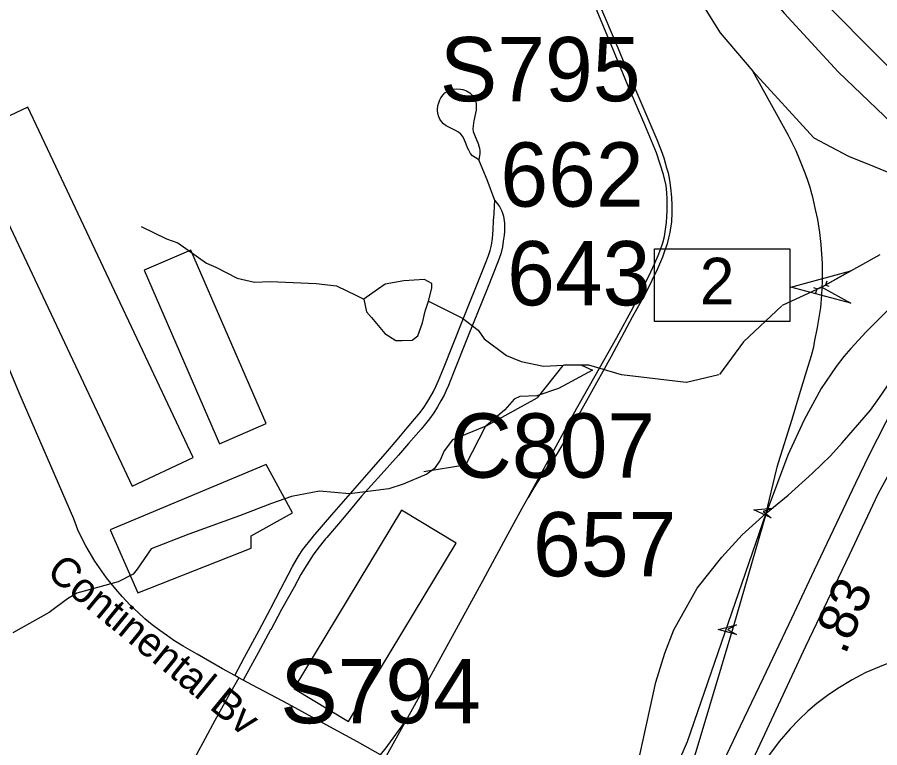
# Model space of a CAD drawing. Extents: x 1383679 to 1536984, y 460658 to 651027.
# Drawn here: x 1423468 to 1426243, y 504390 to 506739 of the extents above; entities that cross this region are included whole.
import ezdxf

# ---------------------------------------------------------------- set-up
doc = ezdxf.new("R2010")
doc.units = 0
for name, color, linetype in [('Exist Cultural Warehouse Building Footprint', 7, 'Continuous'), ('Exist Hydrographic Creek Single Shore', 7, 'Continuous'), ('Exist Hydrographic Misc Water Feature', 7, 'Continuous'), ('Exist Railroad Spur', 7, 'Continuous'), ('Exist Road Non-System Type 51', 7, 'Continuous'), ('Exist Road Non-System Type 51 Label', 7, 'Continuous'), ('Exist Road Primary Interstate Divided Center Attributed', 7, 'Continuous'), ('Exist Road Primary Interstate Interchange CELL', 7, 'Continuous'), ('Exist Road Primary Interstate Ramp 1 Lane Attributed', 7, 'Continuous'), ('Exist Road Primary Interstate Structure Ovrhead Sign Attributed CELL', 7, 'Continuous'), ('Exist Road Primary Interstate Structure Ovrhead Sign Number Label', 7, 'Continuous'), ('Exist Road Secondary Mileage Hundredths English Label', 7, 'Continuous'), ('Exist Road Secondary Structure Culvert Attributed CELL', 7, 'Continuous'), ('Exist Road Secondary Structure Culvert CELL', 7, 'Continuous'), ('Exist Road Secondary Structure Culvert Number Label', 7, 'Continuous'), ('Exist Road Secondary Structure Standard Bridge Attributed CELL', 7, 'Continuous'), ('Exist Road Secondary Structure Standard Bridge Number Label', 7, 'Continuous')]:
    doc.layers.add(name, color=color, linetype=linetype)

msp = doc.modelspace()

# ---------------------------------------------------------------- linework, layer by layer
at = {"layer": 'Exist Cultural Warehouse Building Footprint'}
for points in [[(1423837.8, 505230.9), (1424033.9, 505323.4), (1423502.3, 506450.1), (1423306.1, 506357.6), (1423837.8, 505230.9)], [(1424119, 505367.2), (1424268.9, 505432.3), (1424026.6, 505990.6), (1423876.7, 505925.6), (1424119, 505367.2)], [(1423767.5, 505090.6), (1423855.9, 504888), (1424221.4, 505032.2), (1424221.4, 505071.1), (1424354, 505145.2), (1424269.6, 505301), (1423767.5, 505090.6)], [(1424358, 504580.2), (1424533.9, 504474), (1424880.2, 505047.8), (1424704.2, 505153.9), (1424358, 504580.2)]]:
    msp.add_lwpolyline(points, dxfattribs=at)
at = {"layer": 'Exist Hydrographic Creek Single Shore'}
for p, q in [((1425928.2, 505811.6), (1425805, 505695.4)), ((1425804.6, 505694.9), (1425727.7, 505590)), ((1425224.1, 505619.6), (1425140.6, 505515.2)), ((1425305.9, 505620.8), (1425226.6, 505620.8)), ((1425412.1, 505589.1), (1425306.8, 505620.7)), ((1425620.4, 505564.3), (1425412.7, 505589)), ((1425725.8, 505588.7), (1425621.5, 505564.4)), ((1425139.6, 505514.4), (1424974.9, 505423.2)), ((1424973.6, 505421.8), (1424911.2, 505300.3)), ((1424908.8, 505298.6), (1424776.1, 505277.6))]:
    msp.add_line(p, q, dxfattribs=at)
msp.add_lwpolyline([(1426243.1, 505974.7), (1426056.9, 505871.7), (1425928.9, 505812.1)], dxfattribs=at)
at = {"layer": 'Exist Hydrographic Misc Water Feature'}
for points in [[(1423867.5, 506066.4), (1423948.7, 506026.2), (1423984.5, 506014), (1424077.4, 505948.1), (1424107, 505935.2), (1424176.4, 505900.2), (1424232.2, 505886.8), (1424282.2, 505889.8), (1424430.2, 505882.8), (1424496, 505875.7), (1424559.6, 505844.9), (1424583.3, 505832.1)], [(1424791.3, 505826.3), (1424802, 505867.9), (1424802.4, 505883.5), (1424778.7, 505896.2), (1424712.5, 505891.8), (1424652.3, 505880.8), (1424627.9, 505863.2), (1424583.3, 505832.1)], [(1424583.3, 505832.1), (1424592.5, 505791.7), (1424608.2, 505773.3), (1424651.1, 505722.4), (1424686.8, 505699.6), (1424706.8, 505700), (1424738.8, 505700.9), (1424757, 505714.5), (1424771.9, 505756.1), (1424780.6, 505794.5), (1424791.3, 505826.3)], [(1424791.3, 505826.3), (1424900.3, 505771.5), (1424951.4, 505732.8), (1424971, 505704.5), (1425042, 505651.4), (1425089.6, 505632.3), (1425161.4, 505617), (1425247.5, 505621), (1425283.5, 505620.2), (1425319.2, 505603.9)], [(1425319.2, 505603.9), (1425210, 505545.4), (1425139.5, 505521.4), (1425085.4, 505520), (1425067.2, 505510.5), (1425036.5, 505476.7), (1424975.5, 505424.6), (1424868.6, 505379.9), (1424841.9, 505344.3), (1424829.3, 505315.1), (1424810.8, 505287.5), (1424786.5, 505270), (1424709.8, 505237.1), (1424663.4, 505222.4), (1424537, 505206.9), (1424441.2, 505214.6), (1424350.8, 505198.4), (1424286.3, 505175.8), (1424183.5, 505135.2), (1424020.3, 505077), (1423899.2, 505029.4), (1423854, 504963.8), (1423841.7, 504948.4), (1423793.2, 504923.2), (1423660.4, 504887.3), (1423630, 504868.2), (1423571.2, 504825.1), (1423453.8, 504759.3)]]:
    msp.add_lwpolyline(points, dxfattribs=at)
at = {"layer": 'Exist Railroad Spur'}
for points in [[(1425344.8, 506771.7), (1425395.2, 506653.5), (1425428.9, 506573.8), (1425461.7, 506496.6), (1425526.5, 506346), (1425539.7, 506310.7), (1425548.3, 506287), (1425552.9, 506271.4), (1425557.4, 506254.8), (1425562.1, 506239.1), (1425566.6, 506215.3), (1425570.4, 506190.7), (1425572.9, 506161.1), (1425574.5, 506134.3), (1425574.3, 506111.3), (1425572.7, 506080.1), (1425570.4, 506062.1), (1425567.6, 506047.3), (1425564, 506029.5), (1425558.8, 506011), (1425552.1, 505990.2), (1425543.9, 505967.6), (1425528.2, 505929.9), (1425491.6, 505854.8), (1425446.6, 505775), (1425378.8, 505648.4), (1425304.8, 505515.5), (1425280.3, 505471.5), (1425230.6, 505380.6), (1425215.8, 505353.9), (1425204.9, 505336), (1425192.9, 505316.8), (1425178.3, 505295.2), (1425159.7, 505269.5), (1425143.6, 505245.9), (1425130.7, 505225.3), (1425112.3, 505194.9)], [(1425112.3, 505194.9), (1425208.4, 505371.1), (1425268.9, 505482.3), (1425327.9, 505585.5), (1425396.9, 505709.7), (1425450.1, 505806.3), (1425478.9, 505864.7), (1425500.3, 505906.5), (1425520.1, 505948.7), (1425530.8, 505972.7), (1425538.1, 505992.5), (1425545.8, 506013.3), (1425550.8, 506034.5), (1425553.7, 506056.4), (1425557.3, 506078.8), (1425558.3, 506098.6), (1425559.1, 506116.2), (1425559.6, 506135.9), (1425558.9, 506155.8), (1425558.2, 506174.5), (1425555.7, 506198.3), (1425547.7, 506233.5), (1425525.4, 506303.2), (1425487.6, 506393.1), (1425433.3, 506518.2), (1425381.8, 506643.6), (1425330.3, 506766.2)], [(1424231.6, 503586.9), (1424279, 503674.4), (1424343.4, 503791.2), (1424398.6, 503892.2), (1424468, 504020.3), (1424543.5, 504159.4), (1424575.2, 504216.5), (1424620.2, 504298.3), (1424746.3, 504525.6), (1424966.8, 504928.9), (1425041.8, 505066), (1425093.3, 505160.2), (1425112.3, 505194.9)], [(1424723.1, 504483.8), (1424650.5, 504385.2), (1424602.5, 504328.2), (1424567.9, 504276.9), (1424542.9, 504242.5), (1424531.8, 504224.4), (1424497.7, 504163.7), (1424264.4, 503732.7), (1424228, 503665.9)]]:
    msp.add_lwpolyline(points, dxfattribs=at)
at = {"layer": 'Exist Road Non-System Type 51'}
for p, q in [((1424181.4, 504614.8), (1424168.4, 504621.8)), ((1424194.7, 504607.6), (1424181.4, 504614.8))]:
    msp.add_line(p, q, dxfattribs=at)
for points in [[(1424953.7, 506280.3), (1424941.5, 506287.8), (1424933.2, 506293.9), (1424926.7, 506301.1), (1424920.7, 506311.3), (1424917.4, 506319.1), (1424912.3, 506331.4), (1424904.6, 506349.2), (1424900.3, 506356.9), (1424895.5, 506363.2), (1424887.8, 506369.3), (1424877.9, 506375.2), (1424861.1, 506383.4), (1424848.1, 506390.3), (1424839.4, 506396.7), (1424833.1, 506403.6), (1424828, 506411.5), (1424824.3, 506418.9), (1424821.6, 506430.1), (1424820.8, 506441.9), (1424821.9, 506455.9), (1424824.5, 506464.6), (1424828, 506474.1), (1424831.4, 506480.4), (1424838.3, 506489.7), (1424844.3, 506495.8), (1424851.1, 506500.4), (1424861.4, 506505.6), (1424871.3, 506507.9), (1424881.2, 506508.7), (1424894.1, 506507.9), (1424902.1, 506506.8), (1424913.8, 506502.6), (1424924.5, 506495.8), (1424932.8, 506487.8), (1424938.8, 506480), (1424943.4, 506468.8), (1424945.3, 506458.8), (1424945, 506449.5), (1424944.4, 506440.7), (1424943, 506430.7), (1424937.4, 506406.6), (1424935.9, 506399.4), (1424934.7, 506389.1), (1424934.3, 506380.4), (1424935.5, 506372.4), (1424938.9, 506361.4), (1424952, 506329.7), (1424952.6, 506328.4), (1424956, 506317.8), (1424956.7, 506310.2), (1424956.7, 506301.1), (1424953.7, 506280.3)], [(1425004.7, 506149.9), (1424980.3, 506216.3), (1424960.7, 506262.1), (1424953.7, 506280.3)], [(1424168.4, 504621.8), (1424199.6, 504680.6), (1424246.1, 504765.3), (1424282.9, 504836.6), (1424283.8, 504838.3), (1424316.3, 504901), (1424339.9, 504945.8), (1424354.1, 504973.2), (1424373.1, 505006.2), (1424387.1, 505027.4), (1424417.9, 505066), (1424420.3, 505069.1), (1424480.3, 505138.7), (1424540.1, 505207), (1424608.1, 505284.7), (1424659.4, 505343.4), (1424690.2, 505379.7), (1424722.8, 505419.2), (1424746.8, 505447.1), (1424764.5, 505468.4), (1424776.2, 505483.9), (1424786.1, 505498.7), (1424795.6, 505515.6), (1424807.1, 505535.6), (1424814.8, 505551.2), (1424823.9, 505571.5), (1424839.6, 505609.9), (1424901.6, 505766.2), (1424965.3, 505923.5), (1424978.2, 505955.6), (1424984.5, 505972.7), (1424989.4, 505988.7), (1424993.9, 506006.6), (1424997.4, 506027.8), (1424999.3, 506055.5), (1425001, 506085.4), (1425002.2, 506105.8), (1425004.1, 506132.5), (1425004.7, 506149.9)], [(1425004.7, 506149.9), (1425019.7, 506130.7), (1425027.4, 506115.3), (1425032.7, 506099.5), (1425035.7, 506077.5), (1425035.7, 506050.2), (1425034.6, 506038.1), (1425032.1, 506019.1), (1425029.1, 506001.4), (1425023.9, 505978.2), (1425016, 505955.3), (1424981, 505867.7), (1424919.2, 505714.5), (1424871, 505593.2), (1424855.5, 505555.2), (1424848.1, 505538.8), (1424841.4, 505524.3), (1424831.5, 505505.7), (1424820.3, 505486.6), (1424808.1, 505467.4), (1424794.6, 505448), (1424782.1, 505431.4), (1424767.7, 505414.8), (1424751.8, 505396.1), (1424726.9, 505367.9), (1424694.8, 505330.4), (1424639.1, 505268.9), (1424576.1, 505199.4), (1424520.2, 505131.7), (1424464.7, 505066), (1424460.6, 505061.2), (1424435.7, 505030.2), (1424420.7, 505010.2), (1424392.1, 504966.5), (1424381, 504946.9), (1424359.8, 504905.8), (1424319, 504834.2), (1424283.8, 504768.8), (1424283.6, 504768.5), (1424243.5, 504695.2), (1424194.7, 504607.6)], [(1424168.4, 504621.8), (1424128.4, 504643.3), (1424047, 504690.6), (1424002.5, 504716.1), (1423972.6, 504734.9), (1423948.3, 504751.5), (1423927.2, 504766.6), (1423902.9, 504785.6), (1423878.7, 504804.8), (1423857.1, 504824.8), (1423831.2, 504848.8), (1423805.8, 504876.4), (1423785.3, 504900.1), (1423755.4, 504936.6), (1423718.1, 504990.3), (1423689.5, 505039), (1423675.3, 505066), (1423663.6, 505090.6), (1423650.1, 505125.7), (1423477.8, 505523.3), (1423371.5, 505776)], [(1424181.4, 504614.8), (1424147.4, 504554.6), (1424104.4, 504477.1), (1424073.4, 504419.7), (1424043.5, 504366), (1424011.7, 504308), (1423971.9, 504234.6), (1423932.7, 504162.4), (1423895.7, 504096.1), (1423839.9, 503992.8), (1423786.4, 503895.7), (1423746.2, 503820.4), (1423704, 503743.1), (1423651.9, 503650.8), (1423612.7, 503579.4), (1423567.7, 503498.5), (1423538.9, 503446.5), (1423512.9, 503400), (1423485.8, 503350.7), (1423442.9, 503272.5), (1423418.8, 503227.1), (1423393.7, 503181.5), (1423342, 503081.6), (1423316.7, 503038.4)], [(1424687.6, 504338), (1424644.1, 504363), (1424563.1, 504408.6), (1424462.5, 504463.7), (1424338.6, 504531.5), (1424283.8, 504560.3), (1424224.9, 504591.3), (1424194.7, 504607.6)]]:
    msp.add_lwpolyline(points, dxfattribs=at)
at = {"layer": 'Exist Road Primary Interstate Divided Center Attributed'}
for points in [[(1425073.4, 508070.3), (1425293.2, 507637.6), (1425399, 507455), (1425518.2, 507280.7), (1425633.3, 507115.8), (1425745.3, 506973.6), (1425935.9, 506752.3), (1426109.3, 506564), (1426283.5, 506397.8), (1426408.3, 506282.1), (1426521.5, 506191.5)], [(1426691.7, 506209.6), (1426568.6, 506307.6), (1426490.9, 506377.1), (1426275.2, 506575.2), (1426031.5, 506822.2), (1425828.3, 507066), (1425685.2, 507251.7), (1425537.9, 507462.3)], [(1426686.3, 506014.4), (1426599.7, 505864.5), (1426542.3, 505765.1), (1426506.1, 505699.7), (1426377.5, 505463.2), (1426237.1, 505204.9), (1426144.4, 505009.5), (1426004.8, 504715.5), (1425865.1, 504416.2), (1425744.8, 504158.5), (1425456.4, 503554.4)], [(1426549.7, 505962.5), (1426486, 505856.1), (1426410, 505717.1), (1426340.7, 505590.2), (1426207.5, 505329.8), (1426165, 505240.3), (1426032.4, 504960.5), (1425959.1, 504805.7), (1425867.8, 504613.3)], [(1425867.8, 504613.3), (1425781.7, 504432.3), (1425720.5, 504303.8), (1425682.7, 504218.4), (1425644.1, 504136.5), (1425483.6, 503795.2), (1425457.6, 503740), (1425410.2, 503650.8), (1425369.5, 503582.5), (1425316.7, 503493.1), (1425248.8, 503376.6), (1425114.8, 503176.5)]]:
    msp.add_lwpolyline(points, dxfattribs=at)
at = {"layer": 'Exist Road Primary Interstate Interchange CELL'}
msp.add_lwpolyline([(1425518.9, 505994.1), (1425953.9, 505994.1), (1425953.9, 505760.9), (1425518.9, 505760.9)], close=True, dxfattribs=at)
at = {"layer": 'Exist Road Primary Interstate Ramp 1 Lane Attributed'}
for points in [[(1425073.4, 508070.3), (1425105.5, 507938.5), (1425226.8, 507621), (1425349.2, 507339.9), (1425453.7, 507130.1), (1425729.9, 506688.9), (1425835, 506566.3)], [(1425835, 506566.3), (1426031.5, 506352), (1426142.7, 506292.4), (1426225.3, 506258.9), (1426334.2, 506214.2), (1426412.4, 506199.7), (1426521.5, 506191.5)], [(1426043, 505741.6), (1426053.1, 505805.7), (1426057.3, 505847), (1426059.1, 505889.9), (1426059.1, 505947.4), (1426054.9, 506008.2), (1426050.1, 506046.9), (1426043.7, 506089.1), (1426036.5, 506120.6), (1426027.5, 506160.3), (1426025.1, 506170.9), (1426018.8, 506191.7), (1426011.2, 506217.1), (1426003.5, 506237.8), (1425986.3, 506280.7), (1425974.6, 506309.9), (1425949.3, 506359.1), (1425835, 506566.3)], [(1426686.3, 506040.2), (1426674.4, 506036.2), (1426630, 506020.2), (1426590.9, 506003.9), (1426514.2, 505968.2), (1426446.8, 505930.6), (1426409.6, 505907.2), (1426349.2, 505865.8), (1426288.9, 505817), (1426259, 505787.3), (1426199.1, 505727.8), (1426149.8, 505674.1), (1426128, 505648.2), (1426103.1, 505616), (1426054.9, 505545.3), (1426000.2, 505444.6), (1425947.7, 505330.8), (1425878.2, 505144.8)], [(1425878.2, 505144.8), (1425948, 505201.8), (1426026.7, 505273.3), (1426055.7, 505301.1), (1426084.7, 505328.9), (1426122.5, 505370.6), (1426178.9, 505436.2), (1426213, 505476), (1426240.6, 505513.3), (1426268.6, 505553.8), (1426323.8, 505639.6), (1426369.6, 505715), (1426474.5, 505887.9), (1426506.5, 505940.6)], [(1425878.2, 505144.8), (1425910.9, 505283.2), (1425913.2, 505292.2), (1425917.6, 505306.9), (1425961.6, 505446.6), (1425988.7, 505536.2), (1426013.1, 505616.9), (1426023.4, 505651), (1426030.6, 505679.5), (1426033.6, 505694.2), (1426043, 505741.6)], [(1425878.2, 505144.8), (1425773.5, 504785.6), (1425655.2, 504387.5), (1425607.9, 504234.8), (1425584.2, 504161.9), (1425539.6, 504039.3), (1425504.2, 503949.7), (1425483, 503898.6), (1425469, 503865), (1425385.8, 503679.5), (1425292.7, 503505.5), (1425143.4, 503253.8), (1425114.8, 503176.5)], [(1425197.5, 503502.2), (1425252.8, 503589.8), (1425310.8, 503708), (1425383, 503868.8), (1425491.4, 504114), (1425542.3, 504220.1), (1425624.3, 504409.4), (1425878.2, 505144.8)], [(1425197.5, 503502.2), (1425254.4, 503618.2), (1425312.4, 503748.5), (1425358.4, 503874.3), (1425394.5, 504010), (1425436.1, 504184), (1425472.2, 504371.1), (1425523.1, 504600.9), (1425551.6, 504694), (1425581.1, 504769.5), (1425656.1, 504903), (1425734.9, 505002.5), (1425800.5, 505074.8), (1425878.2, 505144.8)], [(1427109.6, 504590.6), (1426856.7, 504653.1), (1426755.4, 504679.5), (1426731.6, 504685.7), (1426707.7, 504690.7), (1426680.2, 504696.5), (1426648.1, 504701.2), (1426605.5, 504705.9), (1426565, 504708), (1426505.3, 504709), (1426461.1, 504706.3), (1426422, 504701.6), (1426380.5, 504693.6), (1426335, 504681.3), (1426301.2, 504672.2), (1426255.5, 504655.3), (1426198.7, 504632), (1426182.2, 504623.4), (1426153.9, 504608.7), (1426107.8, 504580.3), (1426075.3, 504558.2), (1426041.1, 504532.1), (1426011.4, 504507)], [(1426011.4, 504507), (1425983, 504479), (1425954.6, 504450.9), (1425920, 504410), (1425888.5, 504368), (1425859.2, 504323.1), (1425834.8, 504283.4), (1425813.8, 504245.7), (1425787.1, 504197.6), (1425753.6, 504129.2), (1425456.4, 503554.4)]]:
    msp.add_lwpolyline(points, dxfattribs=at)
at = {"layer": 'Exist Road Primary Interstate Structure Ovrhead Sign Attributed CELL'}
msp.add_lwpolyline([(1425782, 504754.1), (1425723.1, 504769.8), (1425782, 504785.6), (1425753.6, 504769.8)], close=True, dxfattribs=at)
at = {"layer": 'Exist Road Secondary Structure Culvert Attributed CELL'}
msp.add_lwpolyline([(1426150, 505820), (1425956.9, 505871.7), (1426150, 505923.5), (1426056.9, 505871.7)], close=True, dxfattribs=at)
at = {"layer": 'Exist Road Secondary Structure Culvert CELL'}
for p, q in [((1426072.8, 505890.2), (1426068.8, 505878.1)), ((1426029.6, 505870), (1426041.4, 505865.3)), ((1426037.4, 505853.3), (1426041.4, 505865.3)), ((1426041.4, 505865.3), (1426068.8, 505878.1)), ((1426080.6, 505873.5), (1426068.8, 505878.1))]:
    msp.add_line(p, q, dxfattribs=at)
at = {"layer": 'Exist Road Secondary Structure Standard Bridge Attributed CELL'}
msp.add_lwpolyline([(1425893.8, 505129.5), (1425838.5, 505155.1), (1425899.2, 505160.6), (1425868.5, 505149.9)], close=True, dxfattribs=at)

# ---------------------------------------------------------------- texts
at = {"layer": 'Exist Road Non-System Type 51 Label'}
msp.add_text('Continental Bv', height=95, rotation=320.7342, dxfattribs=at).set_placement((1423558.3, 504946.5))
at = {"layer": 'Exist Road Primary Interstate Interchange CELL'}
msp.add_text('2', height=150, dxfattribs=at).set_placement((1425664.1, 505815.7))
at = {"layer": 'Exist Road Primary Interstate Structure Ovrhead Sign Number Label'}
for s, p in [('S795', (1424828, 506469.1)), ('S794', (1424314.7, 504468.4))]:
    msp.add_text(s, height=206.69, dxfattribs=at).set_placement(p)
at = {"layer": 'Exist Road Secondary Mileage Hundredths English Label'}
msp.add_text('.83', height=125, rotation=66.9911, dxfattribs=at).set_placement((1426131.9, 504685.8))
at = {"layer": 'Exist Road Secondary Structure Culvert Number Label'}
msp.add_text('C807', height=206.69, dxfattribs=at).set_placement((1424859.8, 505258.5))
at = {"layer": 'Exist Road Secondary Structure Standard Bridge Number Label'}
for s, p in [('662', (1425022.6, 506130.2)), ('643', (1425044.3, 505812.7)), ('657', (1425127.6, 504941.1))]:
    msp.add_text(s, height=206.69, dxfattribs=at).set_placement(p)

doc.saveas('drawing.dxf')
